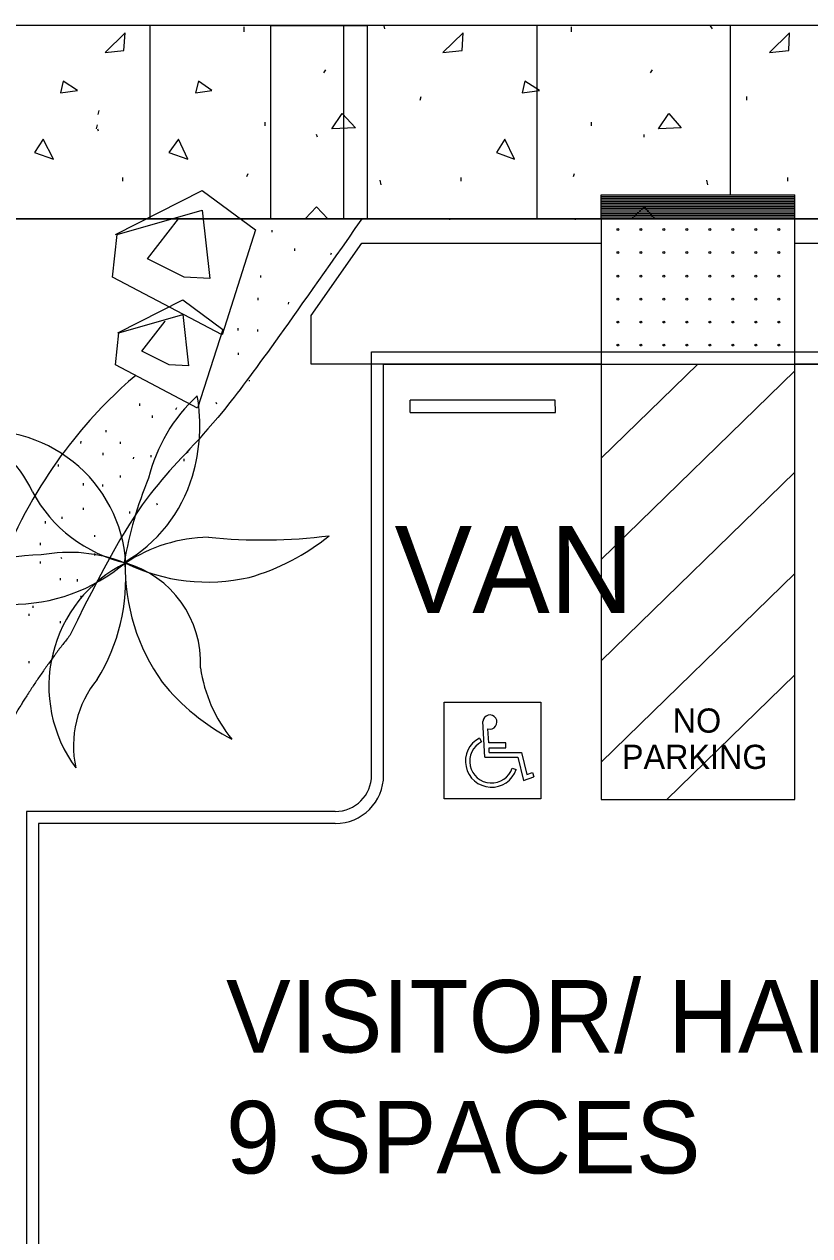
# Model space of a CAD drawing. Extents: x 6712138 to 6712574, y 1869536 to 1870160.
# Drawn here: x 6712496.7 to 6712529.2, y 1869691 to 1869741.1 of the extents above; entities that cross this region are included whole.
import ezdxf

# ---------------------------------------------------------------- set-up
doc = ezdxf.new("R2010")
doc.units = 0
for name, color, linetype in [('A-ANNO-TEXT', 7, 'Continuous'), ('A-COLS', 7, 'Continuous'), ('A-FLOR-CASE', 7, 'Continuous'), ('A-FLOR-PATT', 7, 'Continuous'), ('A-WALL-MBNI', 7, 'Continuous'), ('C-PRKG-CONC', 7, 'Continuous'), ('E-EQPM', 7, 'Continuous'), ('L-Palm', 7, 'Continuous'), ('L-PLNT-PALM', 7, 'Continuous'), ('L-SITE-PAVE', 7, 'Continuous'), ('P-SANR-FIXT', 7, 'Continuous')]:
    doc.layers.add(name, color=color, linetype=linetype)

# ---------------------------------------------------------------- blocks, each defined once
blk = doc.blocks.new('G-handy2')
for p, q in [((0, 0), (-0.0002239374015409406, 0.0035868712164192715)), ((0.000380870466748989, 0.0014482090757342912), (0.0002942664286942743, 0.002835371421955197)), ((-0.000552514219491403, 0.001912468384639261), (-0.0003555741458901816, 0.001537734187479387)), ((0.0020983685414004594, 0.0014486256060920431), (0.000380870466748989, 0.0014482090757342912)), ((0.0020984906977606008, 0.0009449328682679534), (0.0020983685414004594, 0.0014486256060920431)), ((0, 0), (0.0033054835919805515, 8.016511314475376e-07)), ((0.0004123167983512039, 0.0009445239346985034), (0.0020984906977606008, 0.0009449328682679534)), ((0.0004419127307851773, 0.0004704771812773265), (0.0004123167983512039, 0.0009445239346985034)), ((0.0004419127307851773, 0.0004704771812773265), (0.0036734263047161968, 0.00047126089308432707)), ((0.0033054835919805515, 8.016511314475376e-07), (0.0038831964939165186, -0.0023286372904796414)), ((0.0036734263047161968, 0.00047126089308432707), (0.004214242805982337, -0.0017094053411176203)), ((0.002744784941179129, -0.0010810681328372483), (0.00314717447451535, -0.0012125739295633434)), ((0.0038831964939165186, -0.0023286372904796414), (0.004932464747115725, -0.0019506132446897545)), ((0.004214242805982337, -0.0017094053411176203), (0.004773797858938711, -0.0015078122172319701)), ((0.004773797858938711, -0.0015078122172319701), (0.004932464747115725, -0.0019506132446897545))]:
    blk.add_line(p, q)
for centre, radius, start, end in [((0.000485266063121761, 0.0035214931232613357), 0.0007122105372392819, 254.44408755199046, 174.7330607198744), ((0.0006632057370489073, -0.0004007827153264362), 0.0026132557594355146, 117.72399317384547, 341.90197805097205), ((0.0006632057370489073, -0.0004007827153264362), 0.002189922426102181, 117.72399317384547, 341.90197805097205)]:
    blk.add_arc(centre, radius, start, end)
blk = doc.blocks.new('PALM_1')
at = {"layer": 'L-Palm'}
for centre, radius, start, end in [((0.3858816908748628, 0.09873325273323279), 0.34221757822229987, 132.68010435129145, 166.81114852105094), ((-0.21143464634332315, 0.28561485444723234), 0.37101049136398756, 343.75222667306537, 10.043027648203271), ((-0.2899606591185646, -0.022563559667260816), 0.2967686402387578, 4.087292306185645, 99.25548110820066), ((-0.39302858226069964, 0.05608944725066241), 0.22128274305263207, 24.255185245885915, 75.5182453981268), ((-0.15274376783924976, 0.2676552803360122), 0.3096398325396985, 300.1112673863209, 343.904156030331), ((0.8252462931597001, -0.13741070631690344), 0.8340140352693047, 157.86674178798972, 170.53070431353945), ((0.0708143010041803, 0.2901008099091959), 0.2986187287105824, 208.6353551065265, 257.4748050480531), ((0.18676748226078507, -0.2704983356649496), 0.3242322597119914, 91.33821581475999, 124.03846979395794), ((0.28486508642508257, 1.1557831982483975), 1.1071917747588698, 264.52338670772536, 277.67922172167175), ((0.135809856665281, 0.4172046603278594), 0.46568911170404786, 286.170218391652, 309.6262415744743), ((-0.15629416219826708, -0.4705840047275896), 0.4851124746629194, 91.86864634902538, 124.78454736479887), ((-0.11167863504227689, -0.3018879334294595), 0.3218826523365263, 68.83970088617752, 100.82163772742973), ((-0.23642088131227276, 0.2824980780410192), 0.3725896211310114, 270.04016442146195, 310.28947437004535), ((0.13458695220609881, -0.25968764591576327), 0.2885535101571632, 116.79246646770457, 216.83420096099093), ((-0.3945711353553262, -0.03767575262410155), 0.40067112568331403, 328.61828925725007, 5.092334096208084), ((0.4257094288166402, -0.005139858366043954), 0.4211708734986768, 179.48335083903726, 215.7869865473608), ((-0.05353262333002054, -0.21154565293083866), 0.21808204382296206, 357.61340264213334, 74.5522287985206), ((0.17555123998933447, 0.35411295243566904), 0.3945638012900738, 244.43426343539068, 283.17767034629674), ((-0.4218083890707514, -1.038616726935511), 0.9665224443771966, 78.92586106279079, 90.6662430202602), ((0.46385654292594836, -0.1764782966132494), 0.3027327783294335, 188.38557403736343, 219.82450952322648), ((0.11976543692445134, -0.3851968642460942), 0.22128274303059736, 141.1268158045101, 192.38987595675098), ((0.4441476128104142, 0.043868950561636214), 0.46568911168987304, 219.35404246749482, 242.81006565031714)]:
    blk.add_arc(centre, radius, start, end, dxfattribs=at)

msp = doc.modelspace()

# ---------------------------------------------------------------- linework, layer by layer
at = {"layer": 'A-FLOR-CASE'}
for points in [[(6712495.057149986, 1869765.1727473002), (6712479.05714529, 1869765.1727473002), (6712479.057145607, 1869725.672748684), (6712495.07073085, 1869725.6727812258), (6712495.07073085, 1869733.0729383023), (6712560.557711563, 1869733.0729017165), (6712560.557711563, 1869741.0728234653), (6712495.07073085, 1869741.0729369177)], [(6712510.654857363, 1869732.072929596), (6712520.557761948, 1869732.0729240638), (6712520.557778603, 1869727.0727714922), (6712508.557759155, 1869727.0727714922), (6712508.557760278, 1869729.0823763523)], [(6712528.557761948, 1869732.0729195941), (6712555.557759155, 1869732.0729195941), (6712555.557759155, 1869727.0727714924), (6712528.557761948, 1869727.0727714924)]]:
    msp.add_lwpolyline(points, close=True, dxfattribs=at)
at = {"layer": 'A-FLOR-PATT'}
for p, q in [((6712511.609380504, 1869740.9306967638), (6712511.579380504, 1869741.0506967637)), ((6712525.159380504, 1869740.9306967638), (6712525.079380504, 1869741.0506967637)), ((6712505.789380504, 1869740.8106967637), (6712505.789380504, 1869741.0106967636)), ((6712519.329380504, 1869740.8106967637), (6712519.329380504, 1869741.0106967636)), ((6712509.089380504, 1869739.1206967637), (6712509.169380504, 1869739.2406967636)), ((6712522.599380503, 1869739.1206967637), (6712522.6793805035, 1869739.2406967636)), ((6712513.069380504, 1869737.9806967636), (6712513.109380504, 1869738.1406967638)), ((6712526.569380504, 1869737.9806967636), (6712526.569380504, 1869738.1406967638)), ((6712499.759380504, 1869737.3906967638), (6712499.799380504, 1869737.5506967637)), ((6712506.659380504, 1869736.9206967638), (6712506.659380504, 1869737.0806967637)), ((6712520.159380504, 1869736.9206967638), (6712520.159380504, 1869737.0806967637)), ((6712499.689380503, 1869736.8006967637), (6712499.7193805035, 1869736.9606967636)), ((6712499.7193805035, 1869736.8006967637), (6712499.759380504, 1869736.7206967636)), ((6712508.819380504, 1869736.4506967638), (6712508.779380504, 1869736.5606967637)), ((6712522.329380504, 1869736.4506967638), (6712522.329380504, 1869736.5606967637)), ((6712500.779380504, 1869734.6406967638), (6712500.779380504, 1869734.7906967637)), ((6712505.899380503, 1869734.8306967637), (6712505.949380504, 1869734.9506967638)), ((6712511.459380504, 1869734.4806967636), (6712511.419380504, 1869734.6806967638)), ((6712514.759380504, 1869734.6406967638), (6712514.759380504, 1869734.7906967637)), ((6712519.409380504, 1869734.8306967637), (6712519.449380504, 1869734.9506967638)), ((6712524.959380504, 1869734.4806967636), (6712524.919380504, 1869734.6806967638)), ((6712528.269380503, 1869734.6406967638), (6712528.269380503, 1869734.7906967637)), ((6712514.298867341, 1869733.0299371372), (6712514.298867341, 1869733.07292756)), ((6712519.488867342, 1869733.0299371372), (6712519.488867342, 1869733.0729246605)), ((6712506.013283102, 1869732.8012287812), (6712506.013283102, 1869732.810385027)), ((6712506.95063241, 1869732.5275175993), (6712506.95063241, 1869732.6139175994)), ((6712507.886883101, 1869731.7535850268), (6712507.886883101, 1869731.8471850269)), ((6712509.370083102, 1869731.599985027), (6712509.406883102, 1869731.673585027)), ((6712506.483683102, 1869730.653585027), (6712506.483683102, 1869730.736785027)), ((6712506.363683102, 1869729.7103850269), (6712506.363683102, 1869729.803985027)), ((6712507.6236831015, 1869729.5535850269), (6712507.633283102, 1869729.6271850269)), ((6712505.546083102, 1869728.456785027), (6712505.546083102, 1869728.550385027)), ((6712506.350083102, 1869728.416785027), (6712506.350083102, 1869728.500785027)), ((6712505.553283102, 1869727.447185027), (6712505.553283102, 1869727.5335850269)), ((6712506.013283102, 1869726.364440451), (6712506.013283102, 1869726.407185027)), ((6712501.482883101, 1869725.350385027), (6712501.482883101, 1869725.4439850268)), ((6712502.966083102, 1869725.196785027), (6712503.002883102, 1869725.270385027)), ((6712504.659683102, 1869725.416785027), (6712504.633283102, 1869725.480785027)), ((6712502.003626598, 1869724.853316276), (6712502.003626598, 1869724.9397162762)), ((6712500.079683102, 1869724.250385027), (6712500.079683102, 1869724.333585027)), ((6712499.032483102, 1869723.7935850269), (6712499.049283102, 1869723.887185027)), ((6712500.671740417, 1869723.775122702), (6712500.671740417, 1869723.8615227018)), ((6712503.462883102, 1869723.4007850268), (6712503.462883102, 1869723.4839850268)), ((6712499.959683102, 1869723.3071850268), (6712499.959683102, 1869723.4007850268)), ((6712501.219683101, 1869723.1503850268), (6712501.229283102, 1869723.2239850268)), ((6712501.939683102, 1869723.2239850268), (6712501.949283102, 1869723.300785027)), ((6712503.309283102, 1869723.060785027), (6712503.309283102, 1869723.147185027)), ((6712498.118883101, 1869722.833585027), (6712498.118883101, 1869722.9207850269)), ((6712499.142083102, 1869722.0535850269), (6712499.142083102, 1869722.147185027)), ((6712499.946083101, 1869722.0135850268), (6712499.946083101, 1869722.0975850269)), ((6712500.671740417, 1869722.3798133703), (6712500.671740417, 1869722.4662133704)), ((6712499.149283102, 1869721.043985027), (6712499.149283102, 1869721.1303850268)), ((6712502.206083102, 1869721.240785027), (6712502.176483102, 1869721.303985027)), ((6712497.572483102, 1869720.4839850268), (6712497.572483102, 1869720.570385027)), ((6712498.261660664, 1869720.6673882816), (6712498.261660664, 1869720.7537882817)), ((6712501.066083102, 1869720.8903850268), (6712501.066083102, 1869720.977585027)), ((6712499.609283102, 1869719.9303850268), (6712499.609283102, 1869720.0039850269)), ((6712497.3737365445, 1869719.5891947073), (6712497.3737365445, 1869719.6755947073)), ((6712498.255683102, 1869719.0135850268), (6712498.229283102, 1869719.0775850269)), ((6712499.609283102, 1869719.1503850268), (6712499.609283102, 1869719.237585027)), ((6712497.3737365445, 1869718.8281168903), (6712497.3737365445, 1869718.9145168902)), ((6712498.198237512, 1869718.1304622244), (6712498.198237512, 1869718.2168622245)), ((6712498.892483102, 1869718.0871850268), (6712498.892483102, 1869718.173585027)), ((6712499.039952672, 1869717.4320012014), (6712499.049283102, 1869717.4839850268)), ((6712497.058883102, 1869716.9975850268), (6712497.058883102, 1869717.080785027)), ((6712496.905283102, 1869716.657585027), (6712496.905283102, 1869716.7439850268)), ((6712498.198237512, 1869716.3546139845), (6712498.198237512, 1869716.4410139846)), ((6712496.905283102, 1869714.705612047), (6712496.905283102, 1869714.7920120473))]:
    msp.add_line(p, q, dxfattribs=at)
for points in [[(6712500.819380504, 1869740.0306967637), (6712500.869380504, 1869740.7706967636), (6712500.039380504, 1869739.9506967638)], [(6712514.799380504, 1869740.0306967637), (6712514.839380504, 1869740.7706967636), (6712514.009380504, 1869739.9506967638)], [(6712528.309380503, 1869740.0306967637), (6712528.339380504, 1869740.7706967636), (6712527.519380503, 1869739.9506967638)], [(6712498.189380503, 1869738.2906967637), (6712498.899380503, 1869738.3806967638), (6712498.309380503, 1869738.7706967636)], [(6712503.779380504, 1869738.2906967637), (6712504.449380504, 1869738.3806967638), (6712503.899380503, 1869738.7706967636)], [(6712517.279380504, 1869738.2906967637), (6712517.999380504, 1869738.3806967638), (6712517.399380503, 1869738.7706967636)], [(6712509.409380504, 1869736.8006967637), (6712509.839380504, 1869737.4306967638), (6712510.389380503, 1869736.8406967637)], [(6712522.919380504, 1869736.8006967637), (6712523.349380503, 1869737.4306967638), (6712523.859380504, 1869736.8406967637)], [(6712497.119380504, 1869735.8206967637), (6712497.909380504, 1869735.5406967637), (6712497.479380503, 1869736.3706967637)], [(6712502.669380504, 1869735.8206967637), (6712503.459380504, 1869735.5406967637), (6712503.069380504, 1869736.3706967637)], [(6712516.2193805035, 1869735.8206967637), (6712516.9693805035, 1869735.5406967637), (6712516.569380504, 1869736.3706967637)]]:
    msp.add_lwpolyline(points, close=True, dxfattribs=at)
for points in [[(6712508.317815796, 1869733.0729309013), (6712508.779380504, 1869733.5706967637), (6712509.24554267, 1869733.072930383)], [(6712521.822556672, 1869733.0729233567), (6712522.329380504, 1869733.5706967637), (6712522.756043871, 1869733.0729228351)]]:
    msp.add_lwpolyline(points, dxfattribs=at)
at = {"layer": 'A-WALL-MBNI'}
for p, q in [((6712506.876092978, 1869741.0731064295), (6712506.876092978, 1869733.0731057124)), ((6712506.876092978, 1869741.0731064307), (6712510.876092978, 1869741.0731064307)), ((6712510.876092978, 1869741.0731064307), (6712510.876092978, 1869733.0731057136)), ((6712506.876092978, 1869733.0731057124), (6712510.876092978, 1869733.0731057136))]:
    msp.add_line(p, q, dxfattribs=at)
at = {"layer": 'C-PRKG-CONC'}
for p, q in [((6712560.557711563, 1869741.0728234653), (6712495.07073085, 1869741.0729369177)), ((6712560.557711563, 1869733.0729017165), (6712495.07073085, 1869733.0729383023)), ((6712520.557761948, 1869733.0729240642), (6712520.557838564, 1869709.0727361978)), ((6712528.557759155, 1869709.0727714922), (6712528.557761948, 1869733.0729240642)), ((6712511.057838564, 1869727.5727714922), (6712528.55776134, 1869727.5727714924)), ((6712511.057838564, 1869710.0727714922), (6712511.057838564, 1869727.5727714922)), ((6712528.55776134, 1869727.5727714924), (6712556.057744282, 1869727.5727714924)), ((6712511.557838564, 1869710.0727714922), (6712511.557838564, 1869727.0727714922)), ((6712511.557838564, 1869727.0727714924), (6712511.557838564, 1869727.0727714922)), ((6712511.557838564, 1869727.0727714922), (6712528.55776134, 1869727.0727714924)), ((6712520.5577763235, 1869723.1809149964), (6712524.551378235, 1869727.0727714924)), ((6712528.55776134, 1869727.0727714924), (6712555.557759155, 1869727.0727714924)), ((6712520.557794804, 1869718.9919887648), (6712528.557760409, 1869726.7881384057)), ((6712518.65418363, 1869725.5727229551), (6712512.654058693, 1869725.5726964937)), ((6712518.65418363, 1869725.5727229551), (6712512.654058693, 1869725.5726964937)), ((6712512.657287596, 1869725.0726965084), (6712512.654058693, 1869725.5726964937)), ((6712512.657287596, 1869725.0726965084), (6712512.654058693, 1869725.5726964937)), ((6712518.657412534, 1869725.0727229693), (6712518.65418363, 1869725.5727229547)), ((6712518.657412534, 1869725.0727229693), (6712518.65418363, 1869725.5727229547)), ((6712512.657287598, 1869725.0726965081), (6712518.657412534, 1869725.0727229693)), ((6712512.657287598, 1869725.0726965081), (6712518.657412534, 1869725.0727229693)), ((6712520.557813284, 1869714.8030625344), (6712528.55777889, 1869722.5992121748)), ((6712520.557831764, 1869710.6141363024), (6712528.55779737, 1869718.410285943)), ((6712523.27460336, 1869709.072748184), (6712528.557815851, 1869714.2213597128)), ((6712520.557838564, 1869709.0727361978), (6712528.557838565, 1869709.072771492)), ((6712496.792612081, 1869708.5727714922), (6712496.792612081, 1869686.0378687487)), ((6712497.292612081, 1869708.5727714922), (6712496.792612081, 1869708.5727714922)), ((6712509.557854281, 1869708.5727714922), (6712497.292612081, 1869708.572771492)), ((6712509.5578567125, 1869708.0727714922), (6712497.292612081, 1869708.072771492)), ((6712497.292612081, 1869708.072771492), (6712497.292612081, 1869686.5378687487))]:
    msp.add_line(p, q, dxfattribs=at)
msp.add_lwpolyline([(6712518.05781941, 1869709.096003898), (6712514.057819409, 1869709.096003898), (6712514.057819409, 1869713.096003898), (6712518.057819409, 1869713.096003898)], close=True, dxfattribs=at)
for radius, start in [(1.5, 270.0006003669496), (2, 270.0005199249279)]:
    msp.add_arc((6712509.557838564, 1869710.0727714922), radius, start, 0, dxfattribs=at)
at = {"layer": 'E-EQPM'}
for centre in [(6712521.246487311, 1869732.6369056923), (6712522.196487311, 1869732.6369056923), (6712523.146487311, 1869732.6369056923), (6712524.096487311, 1869732.6369056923), (6712525.046487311, 1869732.6369056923), (6712525.996487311, 1869732.6369056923), (6712526.946487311, 1869732.6369056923), (6712527.896487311, 1869732.6369056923), (6712521.246487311, 1869731.6869056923), (6712522.196487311, 1869731.6869056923), (6712523.146487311, 1869731.6869056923), (6712524.096487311, 1869731.6869056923), (6712525.046487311, 1869731.6869056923), (6712525.996487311, 1869731.6869056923), (6712526.946487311, 1869731.6869056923), (6712527.896487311, 1869731.6869056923), (6712521.246487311, 1869730.7079056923), (6712522.196487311, 1869730.7079056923), (6712523.146487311, 1869730.7079056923), (6712524.096487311, 1869730.7079056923), (6712525.046487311, 1869730.7079056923), (6712525.996487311, 1869730.7079056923), (6712526.946487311, 1869730.7079056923), (6712527.896487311, 1869730.7079056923), (6712521.246487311, 1869729.7579056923), (6712522.196487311, 1869729.7579056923), (6712523.146487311, 1869729.7579056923), (6712524.096487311, 1869729.7579056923), (6712525.046487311, 1869729.7579056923), (6712525.996487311, 1869729.7579056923), (6712526.946487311, 1869729.7579056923), (6712527.896487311, 1869729.7579056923), (6712521.246487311, 1869728.8079056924), (6712522.196487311, 1869728.8079056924), (6712523.146487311, 1869728.8079056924), (6712524.096487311, 1869728.8079056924), (6712525.046487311, 1869728.8079056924), (6712525.996487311, 1869728.8079056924), (6712526.946487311, 1869728.8079056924), (6712527.896487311, 1869728.8079056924), (6712521.246487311, 1869727.8579056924), (6712522.196487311, 1869727.8579056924), (6712523.146487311, 1869727.8579056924), (6712524.096487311, 1869727.8579056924), (6712525.046487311, 1869727.8579056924), (6712525.996487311, 1869727.8579056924), (6712526.946487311, 1869727.8579056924), (6712527.896487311, 1869727.8579056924)]:
    msp.add_circle(centre, 0.0375, dxfattribs=at)
at = {"layer": 'L-SITE-PAVE'}
for p, q in [((6712501.891044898, 1869741.0731064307), (6712501.891044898, 1869733.0731064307)), ((6712509.891044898, 1869741.0731064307), (6712509.891044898, 1869733.0731064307)), ((6712517.891044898, 1869741.0732739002), (6712517.891044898, 1869733.0732739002)), ((6712525.891044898, 1869741.0732739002), (6712525.891044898, 1869734.072924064)), ((6712520.557761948, 1869733.0729285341), (6712520.557761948, 1869734.0729285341)), ((6712520.557761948, 1869734.0729285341), (6712528.557761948, 1869734.0729285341)), ((6712528.557761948, 1869733.0729240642), (6712528.557761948, 1869734.0729285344)), ((6712520.557761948, 1869734.0029285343), (6712528.557761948, 1869734.0029285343)), ((6712520.557761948, 1869733.9329285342), (6712528.557761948, 1869733.9329285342)), ((6712520.557761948, 1869733.8629285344), (6712528.557761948, 1869733.8629285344)), ((6712520.557761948, 1869733.7929285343), (6712528.557761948, 1869733.7929285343)), ((6712520.557761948, 1869733.7229285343), (6712528.557761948, 1869733.7229285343)), ((6712520.557761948, 1869733.6529285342), (6712528.557761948, 1869733.6529285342)), ((6712520.557761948, 1869733.5829285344), (6712528.557761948, 1869733.5829285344)), ((6712520.557761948, 1869733.5129285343), (6712528.557761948, 1869733.5129285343)), ((6712520.557761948, 1869733.4429285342), (6712528.557761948, 1869733.4429285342)), ((6712520.557761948, 1869733.3729285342), (6712528.557761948, 1869733.3729285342)), ((6712520.557761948, 1869733.3029285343), (6712528.557761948, 1869733.3029285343)), ((6712520.557761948, 1869733.2329285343), (6712528.557761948, 1869733.2329285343)), ((6712520.557761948, 1869733.1629285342), (6712528.557761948, 1869733.1629285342)), ((6712520.557761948, 1869733.0929285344), (6712528.557761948, 1869733.0929285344)), ((6712520.557761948, 1869733.0729240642), (6712528.557761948, 1869733.0729240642))]:
    msp.add_line(p, q, dxfattribs=at)
for points, degree in [([(6712510.654857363, 1869733.0729295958), (6712507.605052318, 1869728.7318170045), (6712504.572806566, 1869724.408109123), (6712502.098761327, 1869722.2521602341), (6712500.322913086, 1869719.3981184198), (6712498.578776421, 1869715.8464219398)], 3), ([(6712501.304377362, 1869726.6015175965), (6712499.784165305, 1869725.3114697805), (6712495.564194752, 1869720.8782707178), (6712493.629788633, 1869711.743736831), (6712479.057312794, 1869706.5583511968)], 3), ([(6712498.578776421, 1869715.8464219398), (6712495.342213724, 1869711.7754484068), (6712491.853940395, 1869701.5643210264), (6712479.055522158, 1869700.9708899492)], 2)]:
    msp.add_open_spline(points, degree=degree, dxfattribs=at)
at = {"layer": 'P-SANR-FIXT'}
for points in [[(6712500.472503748, 1869732.4277375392), (6712504.059353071, 1869734.2516710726), (6712506.262243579, 1869732.6164203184), (6712504.87739074, 1869728.2767163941), (6712500.346445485, 1869730.6666982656), (6712500.535085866, 1869732.4277375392), (6712504.059353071, 1869733.4340456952), (6712504.374051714, 1869730.6038040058), (6712503.303897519, 1869730.6666982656), (6712501.793880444, 1869731.4214293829), (6712503.077707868, 1869733.0720073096), (6712503.077707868, 1869733.0720073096)], [(6712500.563383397, 1869728.3630262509), (6712503.253520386, 1869729.730976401), (6712504.905688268, 1869728.5045383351), (6712503.867048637, 1869725.249760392), (6712500.468839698, 1869727.0422467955), (6712500.610319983, 1869728.3630262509), (6712503.253520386, 1869729.1177573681), (6712503.489544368, 1869726.9950761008), (6712502.686928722, 1869727.0422467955), (6712501.554415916, 1869727.6082951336), (6712502.517286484, 1869728.8462285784), (6712502.517286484, 1869728.8462285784)]]:
    msp.add_lwpolyline(points, dxfattribs=at)

# ---------------------------------------------------------------- block references
at = {"layer": 'C-PRKG-CONC', "xscale": 412.3229143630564, "yscale": 412.3229143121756, "rotation": -0.2605055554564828}
msp.add_blockref('G-handy2', (6712515.744547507, 1869710.8190794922), dxfattribs=at)
at = {"layer": 'L-PLNT-PALM', "xscale": 19.685039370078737, "yscale": 19.68503937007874, "rotation": -0.36974722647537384}
msp.add_blockref('PALM_1', (6712500.779298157, 1869718.8778223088), dxfattribs=at)

# ---------------------------------------------------------------- texts
at = {"layer": 'A-ANNO-TEXT'}
for s, p in [('VISITOR/ HANDICAP PARKING ', (6712505.0406200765, 1869698.6050266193)), ('9 SPACES', (6712505.0406200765, 1869693.6050266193))]:
    msp.add_text(s, height=3, dxfattribs=at).set_placement(p)
at = {"layer": 'A-COLS'}
msp.add_text('VAN', height=3.6000000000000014, rotation=359.99999232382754, dxfattribs=at).set_placement((6712512.009433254, 1869716.7735180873))
for s, p in [('NO', (6712523.509820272, 1869711.831503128)), ('PARKING', (6712521.413021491, 1869710.331503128))]:
    msp.add_text(s, height=1, dxfattribs=at).set_placement(p)

doc.saveas('drawing.dxf')
